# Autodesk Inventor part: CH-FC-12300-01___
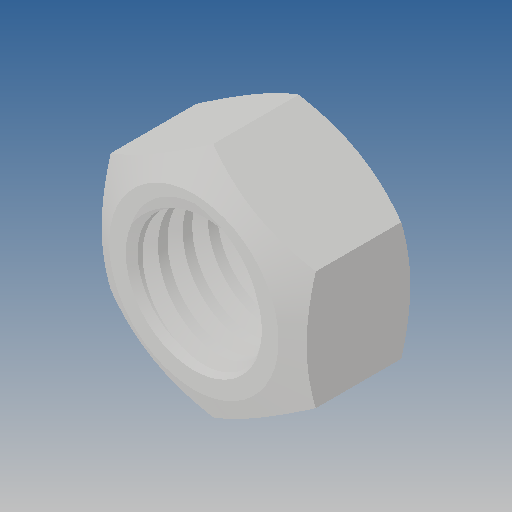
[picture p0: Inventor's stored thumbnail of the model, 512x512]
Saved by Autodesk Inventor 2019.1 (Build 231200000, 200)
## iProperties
Created: 2012-09
Part Number: CH-FC-12300-01___
Material: Ogólny
Document SubType Name: Modeling
Designer: CADENGINEERING4
Density: 1 g/cm^3
Appearance: Domyślna
Author: CADENGINEERING4
Revision Number: ÈÎºÎ
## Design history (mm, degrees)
feature "NONE"
node "Bryła1"
